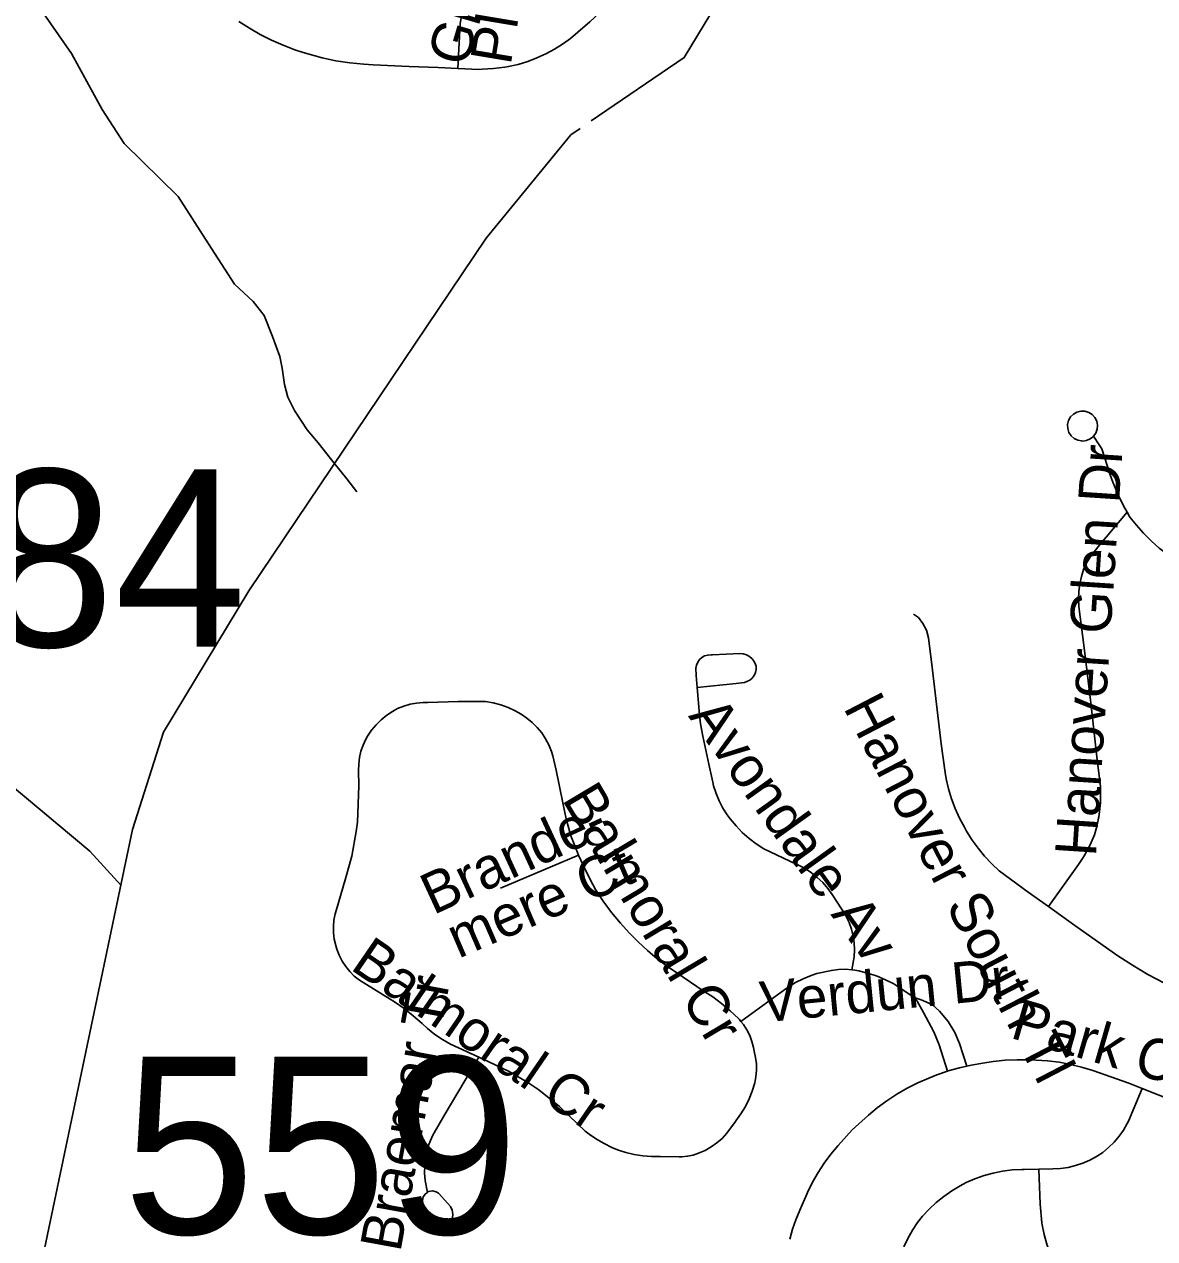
# Model space of a CAD drawing. Extents: x 1383679 to 1536984, y 460658 to 651027.
# Drawn here: x 1438807 to 1441423, y 497325 to 500135 of the extents above; entities that cross this region are included whole.
import ezdxf

# ---------------------------------------------------------------- set-up
doc = ezdxf.new("R2010")
doc.units = 0
for name, color, linetype in [('Exist Hydrographic Creek Single Shore', 7, 'Continuous'), ('Exist Hydrographic Misc Water Feature', 7, 'Continuous'), ('Exist Road Non-System Type 51', 7, 'Continuous'), ('Exist Road Non-System Type 51 Label', 7, 'Continuous'), ('Exist Road Primary Interstate Structure Ovrhead Sign Number Label', 7, 'Continuous'), ('Exist Road Secondary Structure Standard Bridge Number Label', 7, 'Continuous')]:
    doc.layers.add(name, color=color, linetype=linetype)

msp = doc.modelspace()

# ---------------------------------------------------------------- linework, layer by layer
at = {"layer": 'Exist Hydrographic Creek Single Shore'}
for points in [[(1440119.4, 499911.7), (1440334.3, 500058.1), (1440583.3, 500470), (1440732.3, 500893.7), (1440895.3, 501605.9), (1440990.3, 501787.8)], [(1439327.3, 498824.5), (1439876.3, 499640.6), (1440072.3, 499879.6), (1440093.6, 499894.1)], [(1437681.2, 493982.7), (1438070, 494390.1), (1438239.9, 494959), (1438358.6, 495147.7), (1438446.7, 495455.3), (1438472.1, 495837.6), (1438478.3, 495998.8), (1438517.2, 496131.6), (1438636.2, 496770.5), (1438828.3, 497176.9), (1439058.2, 498271.9), (1439129.3, 498496.9), (1439327.3, 498824.5)]]:
    msp.add_lwpolyline(points, dxfattribs=at)
at = {"layer": 'Exist Hydrographic Misc Water Feature'}
for points in [[(1438747.2, 500285.3), (1438839.1, 500179.2), (1438916.7, 500067.6), (1438988, 499938.2), (1439038.3, 499859.2), (1439163.8, 499736.9), (1439233.5, 499627.1), (1439293.6, 499534), (1439337, 499493.8)], [(1439337, 499493.8), (1439362.3, 499461.3), (1439381.6, 499412.5), (1439398.7, 499366.2), (1439404.2, 499339.8), (1439409.4, 499302), (1439416.9, 499272.3), (1439432.3, 499241.6), (1439461.6, 499196.7), (1439487.1, 499166.6), (1439524.2, 499119.9), (1439553.6, 499083.2), (1439577, 499053.2)], [(1439031.9, 498142.7), (1438959.5, 498222.1), (1438770.4, 498380.2)]]:
    msp.add_lwpolyline(points, dxfattribs=at)
at = {"layer": 'Exist Road Non-System Type 51'}
for p, q in [((1439810.4, 500033.2), (1439765.4, 500035.3)), ((1440090, 498212.8), (1439909, 498136.5))]:
    msp.add_line(p, q, dxfattribs=at)
for points in [[(1440243, 500258.4), (1440233.3, 500249.5), (1440169.8, 500191.5), (1440116.1, 500140.8), (1440088.2, 500116.7), (1440070.9, 500102.3), (1440052.9, 500089.2), (1440034.1, 500077.4), (1440014.4, 500066.9), (1440014.3, 500066.8), (1439993.5, 500057.3), (1439972.2, 500049.2), (1439950.3, 500042.5), (1439928, 500037.3), (1439919.3, 500035.7), (1439893.4, 500032.7), (1439867.2, 500031.2), (1439859.5, 500031), (1439810.4, 500033.2)], [(1439810.4, 500033.2), (1439815.8, 500136.9), (1439819.3, 500154), (1439828.4, 500169.4), (1439837.8, 500183.5)], [(1439304, 500142), (1439328.4, 500126.1), (1439353.6, 500111.5), (1439379.5, 500098.4), (1439406.2, 500086.6), (1439433.4, 500076.3), (1439453, 500070), (1439496.8, 500057.5), (1439528.6, 500051), (1439560.7, 500046.1), (1439592.9, 500042.7), (1439614.6, 500041.4), (1439697.8, 500037.7), (1439764.7, 500035.3)], [(1441281.6, 499182.4), (1441286.6, 499189.3), (1441289.8, 499198.1), (1441290.6, 499207.4), (1441288.9, 499216.7), (1441284.7, 499225.1), (1441278.4, 499232.1), (1441270.5, 499237.2), (1441261.5, 499239.9), (1441252.1, 499240.2), (1441243, 499237.9), (1441234.8, 499233.3), (1441228.2, 499226.6), (1441223.6, 499218.4), (1441221.3, 499209.3), (1441221.6, 499199.9), (1441224.4, 499190.9), (1441229.5, 499183), (1441236.5, 499176.8), (1441244.9, 499172.6), (1441253.4, 499171), (1441256.5, 499170.9), (1441265.1, 499172.1), (1441273.7, 499175.8), (1441281.1, 499181.6), (1441281.6, 499182.4)], [(1441359.3, 499006.6), (1441351.1, 499021.3), (1441337.9, 499048.2), (1441326.1, 499075.7), (1441319.8, 499092.4), (1441300.4, 499152.5), (1441294.4, 499162.1), (1441281.6, 499182.4)], [(1441177, 498093.6), (1441246.5, 498190.8), (1441257.7, 498206.9), (1441267.6, 498223.9), (1441276.2, 498241.6), (1441283.3, 498259.9), (1441288.8, 498278.8), (1441292.9, 498298), (1441293.3, 498300.5), (1441297.8, 498333.8), (1441297.8, 498371.4), (1441289, 498439.9), (1441274.9, 498565.1), (1441259.9, 498692.7), (1441247.4, 498788.1), (1441246.5, 498805.6), (1441247.2, 498823), (1441249.4, 498840.3), (1441253.2, 498857.3), (1441258.5, 498873.9), (1441262.3, 498883.4), (1441274.4, 498903.6), (1441294.4, 498929.5), (1441359.3, 499006.6)], [(1441894.3, 498736.2), (1441876.8, 498750), (1441857, 498763.8), (1441838.3, 498774.7), (1441816.2, 498785.8), (1441793.5, 498795.5), (1441770.2, 498803.7), (1441746.4, 498810.5), (1441650, 498833.9), (1441590.8, 498848.5), (1441567.2, 498854.3), (1441544.1, 498861.5), (1441521.5, 498870.3), (1441499.4, 498880.5), (1441478.1, 498892.2), (1441457.7, 498905.1), (1441453.4, 498908.1), (1441433.6, 498923.3), (1441414.8, 498939.8), (1441397.1, 498957.4), (1441380.6, 498976.1), (1441365.7, 498995.1), (1441359.3, 499006.6)], [(1441177, 498093.6), (1441129.9, 498127.2), (1441063.4, 498176.7), (1441045.9, 498192.8), (1441029.5, 498210.1), (1441014.3, 498228.4), (1441000.4, 498247.6), (1440987.8, 498267.8), (1440982.6, 498277), (1440971.2, 498298.3), (1440961.3, 498320.2), (1440952.8, 498342.8), (1440945.9, 498365.8), (1440940.4, 498389.3), (1440937.9, 498403.5), (1440928.6, 498470.3), (1440908.9, 498641), (1440899.8, 498715.5), (1440895, 498732.9), (1440886.6, 498749), (1440876.3, 498762.2), (1440865.1, 498770.4)], [(1440364.5, 498600.2), (1440362.2, 498628.1), (1440361.3, 498645.4), (1440362.7, 498652.5), (1440365.6, 498659.2), (1440369.8, 498665.1), (1440375.2, 498669.9), (1440381.5, 498673.5), (1440388.8, 498675.7), (1440396.4, 498676.4), (1440400, 498676.2), (1440463.3, 498679.4), (1440471.1, 498678.5), (1440478.5, 498676), (1440485.3, 498672.2), (1440491.2, 498667), (1440495.9, 498660.8), (1440499.3, 498653.7), (1440500.6, 498649.6), (1440500.5, 498642.3), (1440498.9, 498635.1), (1440495.9, 498628.4), (1440491.4, 498622.5), (1440485.8, 498617.7), (1440479.4, 498614.3), (1440473.6, 498612.5), (1440454.7, 498609.8), (1440364.5, 498600.2)], [(1440722.5, 497947.3), (1440727.2, 497977.2), (1440728.1, 497993.3), (1440727.5, 498009.4), (1440725.3, 498025.4), (1440721.5, 498041.1), (1440716.2, 498056.4), (1440709.4, 498071), (1440708.6, 498072.7), (1440677, 498121.7), (1440666.6, 498135.8), (1440655, 498149), (1440642.3, 498161), (1440628.5, 498171.8), (1440613.9, 498181.4), (1440598.4, 498189.6), (1440593.4, 498191.8), (1440518.8, 498227.5), (1440501.2, 498238.8), (1440484.5, 498251.4), (1440468.8, 498265.3), (1440454.2, 498280.3), (1440440.8, 498296.3), (1440433.8, 498305.7), (1440423.8, 498321.5), (1440415.2, 498338), (1440408, 498355.1), (1440402.4, 498372.9), (1440400.2, 498381.3), (1440391, 498422.8), (1440377.2, 498487.9), (1440372.2, 498516.8), (1440369.8, 498537), (1440364.5, 498600.2)], [(1439859, 497745.2), (1439793.6, 497775), (1439775.1, 497785.7), (1439757.4, 497797.8), (1439740.6, 497811.1), (1439727.9, 497822.7), (1439707.5, 497840.9), (1439686.1, 497857.8), (1439663.8, 497873.5), (1439654.3, 497879.6), (1439582.8, 497923.3), (1439571.1, 497932.7), (1439560.5, 497943.3), (1439551.1, 497954.9), (1439542.9, 497967.5), (1439536.1, 497980.9), (1439530.8, 497994.9), (1439528.2, 498003.9), (1439524.8, 498018.2), (1439522.9, 498032.8), (1439522.6, 498047.6), (1439523.9, 498062.3), (1439526.8, 498076.7), (1439529.7, 498086.6), (1439550.2, 498155.2), (1439565.7, 498210.2), (1439575.4, 498267.4), (1439578.7, 498289), (1439581.6, 498372.8), (1439581.1, 498408.4), (1439581.2, 498423.4), (1439583, 498438.3), (1439586.3, 498452.9), (1439591.2, 498467.1), (1439597.5, 498480.7), (1439601.7, 498488.1), (1439611, 498501.7), (1439621.5, 498514.3), (1439633.2, 498525.8), (1439646, 498536.2), (1439659.7, 498545.3), (1439671.2, 498551.6), (1439685.4, 498557.4), (1439700.2, 498561.8), (1439715.3, 498564.6), (1439730.6, 498565.9), (1439741, 498565.8), (1439811.6, 498567.9), (1439874.8, 498568.1), (1439892.5, 498565), (1439909.9, 498560.4), (1439926.8, 498554.3), (1439943.1, 498546.8), (1439957.1, 498538.9), (1439970.5, 498529.8), (1439982.9, 498519.5), (1439994.3, 498508), (1440004.6, 498495.5), (1440013.5, 498482), (1440021.1, 498467.7), (1440027.3, 498452.7), (1440030.6, 498442.5), (1440038.4, 498409.1), (1440053.6, 498333.6), (1440061.4, 498296.6), (1440072.3, 498257), (1440085.6, 498222.8), (1440090, 498212.8)], [(1440090, 498212.8), (1440100.4, 498189.2), (1440116.5, 498156.2), (1440129.1, 498132.9), (1440147.1, 498106.1), (1440166.4, 498080.2), (1440186.9, 498055.2), (1440206.9, 498033.1), (1440227.5, 498011.8), (1440249.2, 497991.6), (1440272, 497972.6), (1440295.7, 497954.9), (1440317.5, 497940.2), (1440378.5, 497898.9), (1440400.2, 497884.7), (1440421, 497869.2), (1440440.9, 497852.5), (1440459.6, 497834.5), (1440462, 497832.1), (1440465.7, 497827.6)], [(1441587.4, 497854.9), (1441522.9, 497881.3), (1441481.8, 497898.4), (1441444.2, 497916.9), (1441407.3, 497936.8), (1441371.2, 497958.1), (1441338, 497979.3), (1441237.8, 498050.2), (1441177, 498093.6)], [(1440465.7, 497827.6), (1440559, 497895.5), (1440574.9, 497907.2), (1440591.8, 497917.7), (1440609.4, 497926.7), (1440627.7, 497934.4), (1440641.1, 497938.9), (1440675.1, 497945.9), (1440691.2, 497947.9), (1440707.3, 497948.4), (1440722.5, 497947.3)], [(1440722.5, 497947.3), (1440723.5, 497947.3), (1440739.4, 497944.6), (1440740.9, 497944.3), (1440761.2, 497939.1), (1440781.1, 497932.4), (1440800.4, 497924.2), (1440819.1, 497914.5), (1440826.5, 497910.2), (1440866.2, 497883.1)], [(1440866.2, 497883.1), (1440882.7, 497877.8), (1440898.6, 497871.1), (1440909.7, 497865.3), (1440925.2, 497851.4), (1440945.2, 497827.4), (1440960.6, 497802.2), (1440971, 497776.5), (1440987.9, 497724.6)], [(1440866.2, 497883.1), (1440873.7, 497874.6), (1440888.1, 497848.8), (1440911.6, 497804.1), (1440924.3, 497773.5), (1440943.2, 497712.6)], [(1440465.7, 497827.6), (1440471.2, 497820.8), (1440479.2, 497808.5), (1440485.9, 497795.4), (1440491, 497781.7), (1440494.7, 497767.5), (1440496.1, 497759), (1440499.6, 497744.5), (1440501.4, 497729.7), (1440501.7, 497714.9), (1440500.4, 497700), (1440497.6, 497685.4), (1440491.9, 497666.8), (1440484.7, 497648.7), (1440475.9, 497630.9), (1440465.7, 497613.9), (1440454.1, 497597.7), (1440452.9, 497596.1), (1440433, 497568.9), (1440421.9, 497557.2), (1440409.7, 497546.7), (1440396.5, 497537.4), (1440382.5, 497529.5), (1440367.7, 497523), (1440355.1, 497518.7), (1440342, 497515.9), (1440328.7, 497514.6), (1440322.6, 497514.6), (1440278.9, 497515.4), (1440258.8, 497515.3), (1440238.8, 497516.9), (1440218.9, 497520), (1440199.4, 497524.6), (1440180.2, 497530.8), (1440167.2, 497536), (1440148.8, 497545), (1440131.1, 497555.4), (1440114.3, 497567.1), (1440105.3, 497574.2), (1440068, 497609.5), (1440045.6, 497630.6), (1440022.1, 497650.6), (1439997.7, 497669.3), (1439972.3, 497686.7), (1439963.6, 497692.3), (1439929.2, 497712.1), (1439882.4, 497734.5), (1439859, 497745.2)], [(1439740.4, 497432.2), (1439735.3, 497459.9), (1439733.8, 497476.7), (1439733.9, 497493.6), (1439735.5, 497510.4), (1439738.7, 497527), (1439743.4, 497542.7), (1439749.5, 497558), (1439752.7, 497564.6), (1439779.1, 497610.2), (1439859, 497745.2)], [(1440987.9, 497724.6), (1440971.3, 497720.8), (1440944.8, 497713.2), (1440943.2, 497712.6)], [(1441393.9, 497672.9), (1441362.8, 497685.1), (1441279.4, 497714), (1441253.9, 497722), (1441228, 497728.5), (1441201.7, 497733.4), (1441175.2, 497736.7), (1441148.5, 497738.5), (1441132.4, 497738.8), (1441104.5, 497739.2), (1441076.6, 497737.9), (1441048.8, 497735.2), (1441025.5, 497731.6), (1440998.3, 497727), (1440987.9, 497724.6)], [(1440943.2, 497712.6), (1440918.7, 497704), (1440900.3, 497696.5), (1440874.9, 497685.6), (1440850.1, 497673.2), (1440826.1, 497659.4), (1440802.9, 497644.3), (1440780.6, 497627.8), (1440760.5, 497611.2), (1440722.6, 497576.8), (1440690.5, 497540.8), (1440673.8, 497520.9), (1440658.3, 497500), (1440644, 497478.2), (1440631.2, 497455.6), (1440619.7, 497432.3), (1440617.8, 497428), (1440602, 497390.8), (1440592.8, 497369.1), (1440585, 497346.8), (1440578.7, 497324)], [(1441154.6, 497486.1), (1441187.6, 497486.7), (1441205.2, 497487.7), (1441222.8, 497490.2), (1441240, 497494.3), (1441256.8, 497499.9), (1441273, 497507), (1441288.6, 497515.5), (1441302.6, 497524.9), (1441316.3, 497536.1), (1441328.9, 497548.5), (1441340.4, 497562), (1441350.6, 497576.4), (1441359.5, 497591.7), (1441362.3, 497597), (1441393.9, 497672.9)], [(1441494.2, 497632.6), (1441467.8, 497643.7), (1441393.9, 497672.9)], [(1440842.6, 497306.2), (1440851.8, 497325.7), (1440862.3, 497344.5), (1440874.3, 497362.4), (1440885.4, 497376.9), (1440900.8, 497393.4), (1440917.3, 497408.8), (1440934.9, 497423), (1440953.4, 497436), (1440972.8, 497447.6), (1440986.8, 497454.9), (1441007.1, 497463.7), (1441028, 497471.1), (1441049.4, 497477), (1441071.1, 497481.4), (1441093.1, 497484.2), (1441115.2, 497485.4), (1441120.9, 497485.4), (1441154.6, 497486.1)], [(1441275.1, 497123.9), (1441269.5, 497137), (1441262.4, 497149.7), (1441253.9, 497161.6), (1441211.5, 497229.3), (1441199.7, 497249), (1441189.4, 497269.5), (1441180.4, 497290.6), (1441173, 497312.3), (1441167, 497334.5), (1441162.6, 497357), (1441161.9, 497362), (1441157.6, 497405.3), (1441154.6, 497486.1)], [(1439740.4, 497432.2), (1439743, 497433.9), (1439751.7, 497435.6), (1439760.1, 497433.8), (1439766.1, 497430.1), (1439780.8, 497414.2), (1439793.8, 497399.5), (1439797.7, 497391.2), (1439799.1, 497382.2), (1439798.2, 497373.2), (1439794.8, 497364.7), (1439789.2, 497357.5), (1439782.4, 497352.4), (1439778.3, 497350.3), (1439769.4, 497348.4), (1439760.2, 497348.9), (1439751.5, 497351.8), (1439743.8, 497356.9), (1439737.7, 497363.8), (1439734, 497371.4), (1439733.2, 497373.9), (1439729, 497413.6), (1439730.7, 497421.7), (1439735.6, 497429), (1439740.4, 497432.2)]]:
    msp.add_lwpolyline(points, dxfattribs=at)

# ---------------------------------------------------------------- texts
at = {"layer": 'Exist Road Non-System Type 51 Label'}
for s, rotation, p in [('Greyleaf', 73.4955, (1439830, 500033.5)), ('Pl', 80.5373, (1439932.7, 500038.9)), ('Hanover Glen Dr', 86.2598, (1441286.9, 498208)), ('Hanover South Tl', 297.397, (1440701.4, 498554.5)), ('Avondale Av', 305.693, (1440342.5, 498534.4)), ('Balmoral Cr', 300.8436, (1440050.2, 498342.3)), ('Brande-', 24.7758, (1439753.7, 498073.4)), ('mere Ct', 23.4293, (1439811.9, 497972.6)), ('Balmoral Cr', 325.5523, (1439559, 497949.9)), ('Verdun Dr', 5.6195, (1440514.8, 497825.1)), ('Braemar Tr', 79.623, (1439677.4, 497291.9)), ('Park Crossing Dr', 343.8182, (1441085.9, 497790.5))]:
    msp.add_text(s, height=95, rotation=rotation, dxfattribs=at).set_placement(p)
at = {"layer": 'Exist Road Primary Interstate Structure Ovrhead Sign Number Label'}
msp.add_text('S884', height=410.1, dxfattribs=at).set_placement((1438040.2, 498695))
at = {"layer": 'Exist Road Secondary Structure Standard Bridge Number Label'}
msp.add_text('559', height=410.1, dxfattribs=at).set_placement((1439035.9, 497336.1))

doc.saveas('drawing.dxf')
